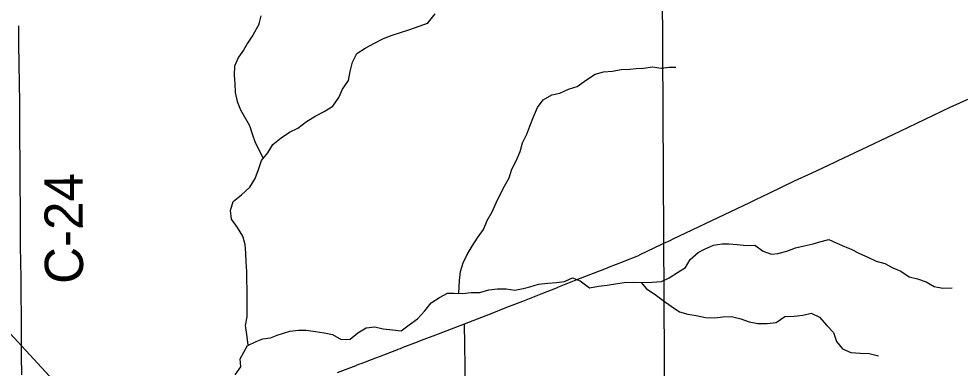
# Model space of a CAD drawing. Extents: x 0 to 34, y 0 to 22.
# Drawn here: x 3.119 to 3.818, y 14.974 to 15.233 of the extents above; entities that cross this region are included whole.
import ezdxf

# ---------------------------------------------------------------- set-up
doc = ezdxf.new("R2010")
doc.units = 0
for name, color, linetype in [('GM_X_Corporation', 7, 'Continuous'), ('GM_X_County_Road', 7, 'Continuous'), ('GM_X_County_Road_Text', 7, 'Continuous'), ('GM_X_Minor_River', 7, 'Continuous'), ('GM_X_Rail_Line', 7, 'Continuous'), ('GM_X_Township_Road', 7, 'Continuous'), ('GM_X_US_Route', 7, 'Continuous')]:
    doc.layers.add(name, color=color, linetype=linetype)

msp = doc.modelspace()

# ---------------------------------------------------------------- linework, layer by layer
at = {"layer": 'GM_X_Corporation'}
msp.add_lwpolyline([(3.60014, 14.75016), (3.59704, 15.30179), (3.59683, 15.37824), (3.4466, 15.37803), (3.44641, 15.42394), (3.59449, 15.49838), (3.75169, 15.57629), (3.75119, 15.61371), (3.73364, 15.61338), (3.72853, 15.57677), (3.59392, 15.50971), (3.59341, 15.52227), (3.59176, 15.56383), (3.61472, 15.56436), (3.61401, 15.61125), (3.56071, 15.6104), (3.55673, 15.67089), (3.51863, 15.67195), (3.51897, 15.6419), (3.50771, 15.64096), (3.50891, 15.60884), (3.31012, 15.60692), (3.31012, 15.63726), (3.31091, 15.7823)], dxfattribs=at)
at = {"layer": 'GM_X_County_Road'}
msp.add_lwpolyline([(3.12161, 14.9687), (3.12145, 14.98272), (3.1214, 14.99018), (3.12134, 14.99798), (3.12122, 15.01198), (3.12101, 15.02897), (3.12097, 15.04057), (3.12071, 15.06423), (3.12066, 15.08265), (3.12056, 15.09211), (3.1204, 15.11023), (3.12035, 15.12361), (3.1201, 15.14803), (3.12, 15.16991), (3.11979, 15.18625), (3.11964, 15.19856), (3.11944, 15.21545), (3.11928, 15.22787)], dxfattribs=at)
at = {"layer": 'GM_X_Minor_River'}
for points in [[(3.2978, 15.22939), (3.29939, 15.23534)], [(3.4227, 15.22955), (3.42861, 15.23695)], [(3.28956, 14.99096), (3.28871, 14.9988), (3.28768, 15.00528), (3.28893, 15.01171), (3.28887, 15.01912), (3.28899, 15.02577), (3.28891, 15.03223), (3.28864, 15.0387), (3.28876, 15.04554), (3.28831, 15.05238), (3.28804, 15.05904), (3.2874, 15.06551), (3.2856, 15.07162), (3.28172, 15.07815), (3.27726, 15.08431), (3.27661, 15.09078), (3.27844, 15.0974), (3.28461, 15.10242), (3.2908, 15.1082), (3.29491, 15.11458), (3.2973, 15.12119), (3.29951, 15.1278), (3.30418, 15.1336), (3.30809, 15.1398), (3.31407, 15.14483), (3.32042, 15.14889), (3.32656, 15.15182), (3.33293, 15.15684), (3.33985, 15.16108), (3.34618, 15.16439), (3.35253, 15.16826), (3.35702, 15.17464), (3.35979, 15.18086), (3.36427, 15.18724), (3.36553, 15.19406), (3.36717, 15.20087), (3.37033, 15.20746), (3.37668, 15.21133), (3.38359, 15.2152), (3.39031, 15.2185), (3.39663, 15.22104), (3.40294, 15.22302), (3.40964, 15.22518), (3.42365, 15.23011)], [(3.2978, 15.22939), (3.29314, 15.22101), (3.28923, 15.21519), (3.28629, 15.20993), (3.28239, 15.20468), (3.27942, 15.19808), (3.2793, 15.19124), (3.27976, 15.18477), (3.28003, 15.17831), (3.28163, 15.17182), (3.28399, 15.16551), (3.29064, 15.15399), (3.29263, 15.14768), (3.2948, 15.14137), (3.30048, 15.13003)], [(3.44621, 15.02946), (3.44673, 15.03869), (3.44742, 15.04552), (3.44925, 15.05195), (3.45221, 15.05816), (3.45612, 15.06436), (3.46003, 15.07037), (3.46452, 15.07675), (3.4671, 15.08335), (3.47083, 15.08975), (3.4738, 15.09653), (3.47676, 15.10275), (3.4801, 15.10896), (3.48344, 15.11498), (3.48546, 15.12159), (3.489, 15.12818), (3.49177, 15.13459), (3.49341, 15.14102), (3.49675, 15.14742), (3.49876, 15.15346), (3.50154, 15.16044), (3.50452, 15.16723), (3.5088, 15.17304), (3.51514, 15.17672), (3.52125, 15.17794), (3.52758, 15.18087), (3.53408, 15.18284), (3.54102, 15.18785), (3.54737, 15.1921), (3.55349, 15.19389), (3.56016, 15.19434), (3.56665, 15.19555), (3.57312, 15.19582), (3.57788, 15.1963), (3.5834, 15.19639), (3.59008, 15.19741), (3.59634, 15.19654), (3.60244, 15.19719), (3.6072, 15.19729)], [(3.55642, 15.03538), (3.56255, 15.03622), (3.56884, 15.03725), (3.5757, 15.03751), (3.58292, 15.03738), (3.58978, 15.03763), (3.59663, 15.03808), (3.60239, 15.04082), (3.60854, 15.0447), (3.6145, 15.04839), (3.61803, 15.05441), (3.62383, 15.05963), (3.62863, 15.06201), (3.63534, 15.06493), (3.64182, 15.06595), (3.64658, 15.06606), (3.65285, 15.06556), (3.65969, 15.06487), (3.66597, 15.06494), (3.67217, 15.06046), (3.67841, 15.05826), (3.68317, 15.05893), (3.68967, 15.06053), (3.69618, 15.06307), (3.70267, 15.06447), (3.70936, 15.06606), (3.71414, 15.0675), (3.72083, 15.06927), (3.72687, 15.06651), (3.73253, 15.06393), (3.73744, 15.06194), (3.74367, 15.05879), (3.7499, 15.05621), (3.75613, 15.05325), (3.76256, 15.05142), (3.76859, 15.04808), (3.77445, 15.0457), (3.78066, 15.0416), (3.78691, 15.03996), (3.79334, 15.03776), (3.79917, 15.03423), (3.80562, 15.03316), (3.81247, 15.03323)], [(3.28952, 14.99043), (3.29566, 14.99354), (3.30064, 14.99554), (3.30636, 14.9962), (3.31115, 14.9982), (3.32071, 15.00107), (3.327, 15.00191), (3.33271, 15.002), (3.33973, 15.00092), (3.34618, 14.99985), (3.35225, 14.9986), (3.35865, 14.99488), (3.3655, 14.99513), (3.37111, 14.99997), (3.37726, 15.00366), (3.38374, 15.0043), (3.38999, 15.00286), (3.39683, 15.00217), (3.40328, 15.00148), (3.40925, 15.00574), (3.41542, 15.01038), (3.42085, 15.01636), (3.42571, 15.02216), (3.43187, 15.02623), (3.43763, 15.02936), (3.44239, 15.02946), (3.44885, 15.02916), (3.45533, 15.02999), (3.4618, 15.02987), (3.46849, 15.03184), (3.47478, 15.03268), (3.48125, 15.03256), (3.4877, 15.0315), (3.494, 15.0329), (3.49878, 15.03396), (3.50528, 15.03612), (3.51214, 15.03675), (3.51862, 15.0374), (3.52472, 15.03805), (3.53067, 15.04079), (3.53633, 15.0386), (3.54328, 15.03334), (3.54996, 15.03455), (3.55643, 15.03538)], [(3.58145, 15.03736), (3.5855, 15.03258), (3.5919, 15.02847), (3.59791, 15.024), (3.60392, 15.01971), (3.61013, 15.0156), (3.61619, 15.01379), (3.62245, 15.01272), (3.62927, 15.01127), (3.63592, 15.01115), (3.64221, 15.0118), (3.64869, 15.01206), (3.65551, 15.01042), (3.66174, 15.00802), (3.66819, 15.00696), (3.67504, 15.00683), (3.6819, 15.00747), (3.68826, 15.0121), (3.69511, 15.01236), (3.70159, 15.013), (3.70789, 15.01441), (3.71393, 15.01164), (3.71934, 15.00546), (3.72439, 15.00005), (3.72655, 14.99336), (3.73103, 14.98815), (3.73726, 14.98538), (3.7441, 14.98488), (3.75094, 14.98456), (3.75776, 14.98292)], [(3.28001, 14.96875), (3.28411, 14.97475), (3.28383, 14.98065), (3.28914, 14.99054)]]:
    msp.add_lwpolyline(points, dxfattribs=at)
at = {"layer": 'GM_X_Rail_Line'}
msp.add_lwpolyline([(3.61871, 14.1), (3.55406, 14.25145), (3.50421, 14.3681), (3.47352, 14.43986), (3.45519, 14.48281), (3.41876, 14.56794), (3.38823, 14.63937), (3.37007, 14.6816), (3.36239, 14.69783), (3.35317, 14.71528), (3.34362, 14.73184), (3.33739, 14.74238), (3.33164, 14.75116), (3.31619, 14.77357), (3.30045, 14.794), (3.29002, 14.80653), (3.28097, 14.81674), (3.23774, 14.86367), (3.19667, 14.90827), (3.14505, 14.96453), (3.12154, 14.98992), (3.09564, 15.01802)], dxfattribs=at)
at = {"layer": 'GM_X_Township_Road'}
msp.add_lwpolyline([(3.45102, 14.9596), (3.45033, 15.00651)], dxfattribs=at)
at = {"layer": 'GM_X_US_Route'}
for p, q in [((3.72501, 15.12654), (3.7273, 15.12762)), ((3.59645, 15.06552), (3.59828, 15.0664))]:
    msp.add_line(p, q, dxfattribs=at)
for points in [[(3.7273, 15.12762), (3.74059, 15.13397), (3.774, 15.14982), (3.81102, 15.16755), (3.84687, 15.18352), (3.87695, 15.19692)], [(3.6955, 15.11274), (3.70852, 15.11878), (3.72501, 15.12654)], [(3.66217, 15.09679), (3.66617, 15.09871), (3.67661, 15.1037), (3.6955, 15.11274)], [(3.60541, 15.06964), (3.64805, 15.09004), (3.66217, 15.09679)], [(3.59828, 15.0664), (3.60299, 15.06848), (3.60317, 15.06856), (3.60541, 15.06964)], [(3.35614, 14.97055), (3.36979, 14.97577), (3.37007, 14.97588), (3.37177, 14.97652), (3.37365, 14.97724), (3.38451, 14.98139), (3.38728, 14.98245), (3.40003, 14.98733), (3.4009, 14.98766), (3.40283, 14.9884), (3.4048, 14.98915), (3.41555, 14.99326), (3.41845, 14.99437), (3.43108, 14.9992), (3.45033, 15.00651), (3.46961, 15.01413), (3.48186, 15.01894), (3.49362, 15.02356), (3.50729, 15.02893), (3.5194, 15.03369), (3.51979, 15.03385), (3.53213, 15.03873), (3.5442, 15.04346), (3.55653, 15.0483), (3.55798, 15.04887), (3.56835, 15.05293), (3.56902, 15.05319), (3.57906, 15.05713), (3.58137, 15.05826), (3.59645, 15.06552)]]:
    msp.add_lwpolyline(points, dxfattribs=at)

# ---------------------------------------------------------------- texts
at = {"layer": 'GM_X_County_Road_Text'}
msp.add_text('C-24', height=0.028409, rotation=90.3429, dxfattribs=at).set_placement((3.16714, 15.03634))

doc.saveas('drawing.dxf')
